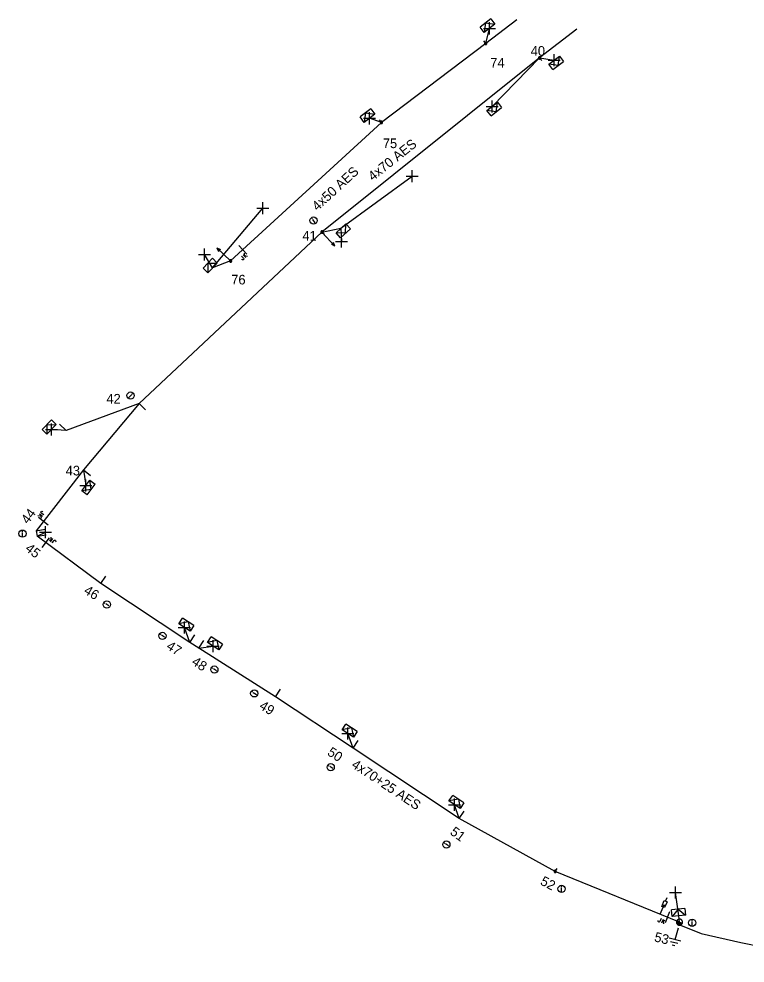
# Model space of a CAD drawing. Extents: x -540247 to -537390, y -1183887 to -1180355.
# Drawn here: x -537803.3 to -537727.9, y -1180528.4 to -1180430.4 of the extents above; entities that cross this region are included whole.
import ezdxf

# ---------------------------------------------------------------- set-up
doc = ezdxf.new("R2010")
doc.units = 0
for name, color, linetype in [('Vrstva 1', 7, 'Continuous'), ('Vrstva 10', 7, 'Continuous'), ('Vrstva 13', 7, 'Continuous'), ('Vrstva 14', 7, 'Continuous'), ('Vrstva 15', 7, 'Continuous'), ('Vrstva 16', 7, 'Continuous'), ('Vrstva 18', 7, 'Continuous'), ('Vrstva 2', 7, 'Continuous'), ('Vrstva 31', 7, 'Continuous'), ('Vrstva 34', 7, 'Continuous'), ('Vrstva 36', 7, 'Continuous'), ('Vrstva 5', 7, 'Continuous'), ('Vrstva 50', 7, 'Continuous'), ('Vrstva 51', 7, 'Continuous'), ('Vrstva 54', 7, 'Continuous'), ('Vrstva 59', 7, 'Continuous'), ('Vrstva 8', 7, 'Continuous'), ('Vrstva 9', 7, 'Continuous')]:
    doc.layers.add(name, color=color, linetype=linetype)

# ---------------------------------------------------------------- blocks, each defined once
blk = doc.blocks.new('NN440')
at = {"layer": 'Vrstva 2'}
for points in [[(0.63, 0), (0.63, 0.06), (0.62, 0.13), (0.6, 0.19), (0.58, 0.25), (0.55, 0.31), (0.51, 0.37), (0.47, 0.42), (0.42, 0.46), (0.37, 0.51), (0.32, 0.54), (0.26, 0.57), (0.2, 0.59), (0.13, 0.61), (0.07, 0.62), (0, 0.63), (-0.06, 0.62), (-0.13, 0.61), (-0.19, 0.59), (-0.26, 0.57), (-0.31, 0.54), (-0.37, 0.51), (-0.42, 0.46), (-0.47, 0.42), (-0.51, 0.37), (-0.54, 0.31), (-0.57, 0.25), (-0.6, 0.19), (-0.62, 0.13), (-0.63, 0.06), (-0.63, 0), (-0.63, -0.07), (-0.62, -0.14), (-0.6, -0.2), (-0.57, -0.26), (-0.54, -0.32), (-0.51, -0.37), (-0.47, -0.43), (-0.42, -0.47), (-0.37, -0.51), (-0.31, -0.55), (-0.26, -0.58), (-0.19, -0.6), (-0.13, -0.62), (-0.06, -0.63), (0, -0.63), (0.07, -0.63), (0.13, -0.62), (0.2, -0.6), (0.26, -0.58), (0.32, -0.55), (0.37, -0.51), (0.42, -0.47), (0.47, -0.43), (0.51, -0.37), (0.55, -0.32), (0.58, -0.26), (0.6, -0.2), (0.62, -0.14), (0.63, -0.07), (0.63, 0)], [(-0.63, 0), (0.63, 0)], [(-0.6, -0.18), (0.57, -0.18)], [(-0.51, -0.32), (0.5, -0.32)], [(-0.37, -0.47), (0.35, -0.47)]]:
    blk.add_lwpolyline(points, dxfattribs=at)
blk = doc.blocks.new('NN560')
at = {"layer": 'Vrstva 2'}
for points in [[(1.999, -0.001), (1.59, 0.141)], [(0, -0.001), (1.999, -0.001)], [(1.999, -0.001), (1.59, -0.134)]]:
    blk.add_lwpolyline(points, dxfattribs=at)
blk = doc.blocks.new('NN840')
at = {"layer": 'Vrstva 15'}
for points in [[(0.003, 0.619), (0.003, -0.631)], [(-0.745, -0.71), (-0.745, -0.66)], [(-0.73, -0.764), (-0.745, -0.71)], [(-0.657, -0.798), (-0.73, -0.764)], [(-0.627, -0.798), (-0.657, -0.798)], [(-0.558, -0.764), (-0.627, -0.798)], [(-0.538, -0.71), (-0.558, -0.764)], [(-0.538, -0.385), (-0.538, -0.71)], [(-0.332, -0.385), (-0.332, -0.798)], [(-0.332, -0.641), (-0.125, -0.385)], [(-0.263, -0.557), (-0.091, -0.798)]]:
    blk.add_lwpolyline(points, dxfattribs=at)
blk = doc.blocks.new('NN770')
at = {"layer": 'Vrstva 10'}
for p, q in [((0.002, 0.187), (0.002, 0.263)), ((0.002, -0.276), (0.002, 0.111))]:
    blk.add_line(p, q, dxfattribs=at)
blk.add_circle((0, -0.008), 0.375, dxfattribs=at)
blk = doc.blocks.new('NN800')
at = {"layer": 'Vrstva 1'}
for points in [[(-0.442, 0.442), (0.442, -0.442)], [(-0.442, -0.442), (0.442, 0.442)]]:
    blk.add_lwpolyline(points, dxfattribs=at)
blk = doc.blocks.new('NN820')
at = {"layer": 'Vrstva 13'}
for points in [[(-0.003, 0.004), (-0.003, -1.049)], [(-0.165, -0.813), (0.165, -0.813)], [(-0.165, -1.473), (-0.165, -0.813)], [(-0.003, -1.049), (-0.062, -0.926)], [(-0.003, -1.049), (0.057, -0.926)], [(0.165, -0.813), (0.165, -1.473)], [(0.165, -1.473), (-0.165, -1.473)], [(-0.003, -1.473), (-0.003, -1.871)]]:
    blk.add_lwpolyline(points, dxfattribs=at)
blk = doc.blocks.new('NN630')
at = {"layer": 'Vrstva 9'}
for points in [[(-0.003, -0.7), (-0.703, 0)], [(-0.703, -0.7), (-0.703, 0), (0.697, 0), (0.697, -0.7)], [(-0.703, -0.7), (0.697, -0.7)], [(-0.003, -0.7), (0.697, 0)]]:
    blk.add_lwpolyline(points, dxfattribs=at)
blk = doc.blocks.new('NN810')
at = {"layer": 'Vrstva 14'}
for points in [[(0.004, -0.64), (0.004, -1.89)], [(0.629, -1.89), (-0.621, -1.89)], [(0.388, -2.2), (-0.399, -2.2)], [(0.004, -2.515), (-0.124, -2.515)], [(0.137, -2.515), (0.004, -2.515)]]:
    blk.add_lwpolyline(points, dxfattribs=at)
blk = doc.blocks.new('NN500')
at = {"layer": 'Vrstva 2'}
for points in [[(0, -0.24), (0.02, -0.23), (0.05, -0.23), (0.07, -0.22), (0.09, -0.22), (0.12, -0.2), (0.14, -0.19), (0.16, -0.18), (0.17, -0.16), (0.19, -0.14), (0.2, -0.12), (0.21, -0.1), (0.22, -0.07), (0.23, -0.05), (0.23, -0.02), (0.23, 0), (0.23, 0.02), (0.23, 0.05), (0.22, 0.07), (0.21, 0.1), (0.2, 0.12), (0.19, 0.14), (0.17, 0.16), (0.16, 0.17), (0.14, 0.19), (0.12, 0.2), (0.09, 0.21), (0.07, 0.22), (0.05, 0.23), (0.02, 0.23), (0, 0.23), (-0.03, 0.23), (-0.05, 0.23), (-0.07, 0.22), (-0.1, 0.21), (-0.12, 0.2), (-0.14, 0.19), (-0.16, 0.17), (-0.18, 0.16), (-0.19, 0.14), (-0.2, 0.12), (-0.22, 0.1), (-0.22, 0.07), (-0.23, 0.05), (-0.23, 0.02), (-0.24, 0), (-0.23, -0.02), (-0.23, -0.05), (-0.22, -0.07), (-0.22, -0.1), (-0.2, -0.12), (-0.19, -0.14), (-0.18, -0.16), (-0.16, -0.18), (-0.14, -0.19), (-0.12, -0.2), (-0.1, -0.22), (-0.07, -0.22), (-0.05, -0.23), (-0.03, -0.23), (0, -0.24)], [(0, -0.24), (0.02, -0.23), (0.05, -0.23), (0.07, -0.22), (0.09, -0.22), (0.12, -0.2), (0.14, -0.19), (0.16, -0.18), (0.17, -0.16), (0.19, -0.14), (0.2, -0.12), (0.21, -0.1), (0.22, -0.07), (0.23, -0.05), (0.23, -0.02), (0.23, 0), (0.23, 0.02), (0.23, 0.05), (0.22, 0.07), (0.21, 0.1), (0.2, 0.12), (0.19, 0.14), (0.17, 0.16), (0.16, 0.17), (0.14, 0.19), (0.12, 0.2), (0.09, 0.21), (0.07, 0.22), (0.05, 0.23), (0.02, 0.23), (0, 0.23), (-0.03, 0.23), (-0.05, 0.23), (-0.07, 0.22), (-0.1, 0.21), (-0.12, 0.2), (-0.14, 0.19), (-0.16, 0.17), (-0.18, 0.16), (-0.19, 0.14), (-0.2, 0.12), (-0.22, 0.1), (-0.22, 0.07), (-0.23, 0.05), (-0.23, 0.02), (-0.24, 0), (-0.23, -0.02), (-0.23, -0.05), (-0.22, -0.07), (-0.22, -0.1), (-0.2, -0.12), (-0.19, -0.14), (-0.18, -0.16), (-0.16, -0.18), (-0.14, -0.19), (-0.12, -0.2), (-0.1, -0.22), (-0.07, -0.22), (-0.05, -0.23), (-0.03, -0.23), (0, -0.24)], [(0, -0.21), (0.02, -0.2), (0.04, -0.2), (0.06, -0.2), (0.08, -0.19), (0.1, -0.18), (0.12, -0.17), (0.14, -0.15), (0.15, -0.14), (0.16, -0.12), (0.18, -0.1), (0.19, -0.08), (0.19, -0.06), (0.2, -0.04), (0.2, -0.02), (0.2, 0), (0.2, 0.02), (0.2, 0.04), (0.19, 0.06), (0.19, 0.08), (0.18, 0.1), (0.16, 0.12), (0.15, 0.14), (0.14, 0.15), (0.12, 0.17), (0.1, 0.18), (0.08, 0.19), (0.06, 0.19), (0.04, 0.2), (0.02, 0.2), (0, 0.2), (-0.02, 0.2), (-0.04, 0.2), (-0.06, 0.19), (-0.08, 0.19), (-0.1, 0.18), (-0.12, 0.17), (-0.14, 0.15), (-0.15, 0.14), (-0.17, 0.12), (-0.18, 0.1), (-0.19, 0.08), (-0.2, 0.06), (-0.2, 0.04), (-0.21, 0.02), (-0.21, 0), (-0.21, -0.02), (-0.2, -0.04), (-0.2, -0.06), (-0.19, -0.08), (-0.18, -0.1), (-0.17, -0.12), (-0.15, -0.14), (-0.14, -0.15), (-0.12, -0.17), (-0.1, -0.18), (-0.08, -0.19), (-0.06, -0.2), (-0.04, -0.2), (-0.02, -0.2), (0, -0.21)], [(0, -0.18), (0.02, -0.18), (0.04, -0.17), (0.05, -0.17), (0.07, -0.16), (0.09, -0.15), (0.1, -0.14), (0.12, -0.13), (0.13, -0.12), (0.14, -0.1), (0.15, -0.09), (0.16, -0.07), (0.17, -0.05), (0.17, -0.04), (0.17, -0.02), (0.17, 0), (0.17, 0.02), (0.17, 0.04), (0.17, 0.05), (0.16, 0.07), (0.15, 0.09), (0.14, 0.1), (0.13, 0.12), (0.12, 0.13), (0.1, 0.14), (0.09, 0.15), (0.07, 0.16), (0.05, 0.17), (0.04, 0.17), (0.02, 0.17), (0, 0.18), (-0.02, 0.17), (-0.04, 0.17), (-0.06, 0.17), (-0.07, 0.16), (-0.09, 0.15), (-0.1, 0.14), (-0.12, 0.13), (-0.13, 0.12), (-0.14, 0.1), (-0.15, 0.09), (-0.16, 0.07), (-0.17, 0.05), (-0.17, 0.04), (-0.18, 0.02), (-0.18, 0), (-0.18, -0.02), (-0.17, -0.04), (-0.17, -0.05), (-0.16, -0.07), (-0.15, -0.09), (-0.14, -0.1), (-0.13, -0.12), (-0.12, -0.13), (-0.1, -0.14), (-0.09, -0.15), (-0.07, -0.16), (-0.06, -0.17), (-0.04, -0.17), (-0.02, -0.18), (0, -0.18)], [(0, -0.15), (0.01, -0.15), (0.03, -0.14), (0.04, -0.14), (0.06, -0.13), (0.07, -0.13), (0.08, -0.12), (0.1, -0.11), (0.11, -0.1), (0.12, -0.09), (0.13, -0.07), (0.13, -0.06), (0.14, -0.05), (0.14, -0.03), (0.14, -0.02), (0.14, 0), (0.14, 0.01), (0.14, 0.03), (0.14, 0.04), (0.13, 0.06), (0.13, 0.07), (0.12, 0.09), (0.11, 0.1), (0.1, 0.11), (0.08, 0.12), (0.07, 0.13), (0.06, 0.13), (0.04, 0.14), (0.03, 0.14), (0.01, 0.14), (0, 0.15), (-0.02, 0.14), (-0.03, 0.14), (-0.05, 0.14), (-0.06, 0.13), (-0.07, 0.13), (-0.09, 0.12), (-0.1, 0.11), (-0.11, 0.1), (-0.12, 0.09), (-0.13, 0.07), (-0.13, 0.06), (-0.14, 0.04), (-0.14, 0.03), (-0.15, 0.01), (-0.15, 0), (-0.15, -0.02), (-0.14, -0.03), (-0.14, -0.05), (-0.13, -0.06), (-0.13, -0.07), (-0.12, -0.09), (-0.11, -0.1), (-0.1, -0.11), (-0.09, -0.12), (-0.07, -0.13), (-0.06, -0.13), (-0.05, -0.14), (-0.03, -0.14), (-0.02, -0.15), (0, -0.15)], [(0, -0.12), (0.01, -0.12), (0.02, -0.11), (0.03, -0.11), (0.05, -0.11), (0.06, -0.1), (0.07, -0.09), (0.08, -0.09), (0.09, -0.08), (0.09, -0.07), (0.1, -0.06), (0.11, -0.05), (0.11, -0.04), (0.11, -0.02), (0.11, -0.01), (0.12, 0), (0.11, 0.01), (0.11, 0.02), (0.11, 0.04), (0.11, 0.05), (0.1, 0.06), (0.09, 0.07), (0.09, 0.08), (0.08, 0.09), (0.07, 0.09), (0.06, 0.1), (0.05, 0.11), (0.03, 0.11), (0.02, 0.11), (0.01, 0.12), (0, 0.12), (-0.01, 0.12), (-0.03, 0.11), (-0.04, 0.11), (-0.05, 0.11), (-0.06, 0.1), (-0.07, 0.09), (-0.08, 0.09), (-0.09, 0.08), (-0.1, 0.07), (-0.1, 0.06), (-0.11, 0.05), (-0.11, 0.04), (-0.12, 0.02), (-0.12, 0.01), (-0.12, 0), (-0.12, -0.01), (-0.12, -0.02), (-0.11, -0.04), (-0.11, -0.05), (-0.1, -0.06), (-0.1, -0.07), (-0.09, -0.08), (-0.08, -0.09), (-0.07, -0.09), (-0.06, -0.1), (-0.05, -0.11), (-0.04, -0.11), (-0.03, -0.11), (-0.01, -0.12), (0, -0.12)], [(0, -0.09), (0.01, -0.09), (0.02, -0.09), (0.03, -0.08), (0.03, -0.08), (0.04, -0.08), (0.05, -0.07), (0.06, -0.07), (0.06, -0.06), (0.07, -0.05), (0.07, -0.04), (0.08, -0.04), (0.08, -0.03), (0.08, -0.02), (0.09, -0.01), (0.09, 0), (0.09, 0.01), (0.08, 0.02), (0.08, 0.03), (0.08, 0.03), (0.07, 0.04), (0.07, 0.05), (0.06, 0.06), (0.06, 0.06), (0.05, 0.07), (0.04, 0.07), (0.03, 0.08), (0.03, 0.08), (0.02, 0.08), (0.01, 0.09), (0, 0.09), (-0.01, 0.09), (-0.02, 0.08), (-0.03, 0.08), (-0.04, 0.08), (-0.04, 0.07), (-0.05, 0.07), (-0.06, 0.06), (-0.07, 0.06), (-0.07, 0.05), (-0.08, 0.04), (-0.08, 0.03), (-0.08, 0.03), (-0.09, 0.02), (-0.09, 0.01), (-0.09, 0), (-0.09, -0.01), (-0.09, -0.02), (-0.08, -0.03), (-0.08, -0.04), (-0.08, -0.04), (-0.07, -0.05), (-0.07, -0.06), (-0.06, -0.07), (-0.05, -0.07), (-0.04, -0.08), (-0.04, -0.08), (-0.03, -0.08), (-0.02, -0.09), (-0.01, -0.09), (0, -0.09)], [(0, -0.06), (0, -0.06), (0.01, -0.06), (0.02, -0.05), (0.02, -0.05), (0.03, -0.05), (0.03, -0.05), (0.04, -0.04), (0.04, -0.04), (0.05, -0.03), (0.05, -0.03), (0.05, -0.02), (0.05, -0.02), (0.05, -0.01), (0.06, -0.01), (0.06, 0), (0.06, 0.01), (0.05, 0.01), (0.05, 0.02), (0.05, 0.02), (0.05, 0.03), (0.05, 0.03), (0.04, 0.04), (0.04, 0.04), (0.03, 0.05), (0.03, 0.05), (0.02, 0.05), (0.02, 0.05), (0.01, 0.06), (0, 0.06), (0, 0.06), (-0.01, 0.06), (-0.01, 0.06), (-0.02, 0.05), (-0.02, 0.05), (-0.03, 0.05), (-0.03, 0.05), (-0.04, 0.04), (-0.04, 0.04), (-0.05, 0.03), (-0.05, 0.03), (-0.05, 0.02), (-0.06, 0.02), (-0.06, 0.01), (-0.06, 0.01), (-0.06, 0), (-0.06, -0.01), (-0.06, -0.01), (-0.06, -0.02), (-0.05, -0.02), (-0.05, -0.03), (-0.05, -0.03), (-0.04, -0.04), (-0.04, -0.04), (-0.03, -0.05), (-0.03, -0.05), (-0.02, -0.05), (-0.02, -0.05), (-0.01, -0.06), (-0.01, -0.06), (0, -0.06)], [(0, -0.03), (0, -0.03), (0, -0.03), (0.01, -0.03), (0.01, -0.03), (0.01, -0.02), (0.02, -0.02), (0.02, -0.02), (0.02, -0.02), (0.02, -0.02), (0.02, -0.01), (0.02, -0.01), (0.03, -0.01), (0.03, -0.01), (0.03, 0), (0.03, 0), (0.03, 0), (0.03, 0.01), (0.03, 0.01), (0.02, 0.01), (0.02, 0.01), (0.02, 0.02), (0.02, 0.02), (0.02, 0.02), (0.02, 0.02), (0.01, 0.02), (0.01, 0.02), (0.01, 0.03), (0, 0.03), (0, 0.03), (0, 0.03), (0, 0.03), (-0.01, 0.03), (-0.01, 0.03), (-0.01, 0.02), (-0.02, 0.02), (-0.02, 0.02), (-0.02, 0.02), (-0.02, 0.02), (-0.02, 0.02), (-0.03, 0.01), (-0.03, 0.01), (-0.03, 0.01), (-0.03, 0.01), (-0.03, 0), (-0.03, 0), (-0.03, 0), (-0.03, -0.01), (-0.03, -0.01), (-0.03, -0.01), (-0.03, -0.01), (-0.02, -0.02), (-0.02, -0.02), (-0.02, -0.02), (-0.02, -0.02), (-0.02, -0.02), (-0.01, -0.03), (-0.01, -0.03), (-0.01, -0.03), (0, -0.03), (0, -0.03)], [(0.23, 0), (0.7, 0)]]:
    blk.add_lwpolyline(points, dxfattribs=at)
blk = doc.blocks.new('NN510')
at = {"layer": 'Vrstva 2'}
blk.add_lwpolyline([(0.001, 0.002), (0.001, 0.939)], dxfattribs=at)

msp = doc.modelspace()

# ---------------------------------------------------------------- linework, layer by layer
at = {"layer": 'Vrstva 5'}
msp.add_lwpolyline([(-537734.68, -1180524.19), (-537734.74, -1180524.45), (-537732.42, -1180525.38), (-537728.3, -1180526.32), (-537725.94, -1180526.78), (-537719.916, -1180528.443), (-537719.145, -1180526.532), (-537715.575, -1180518.142), (-537712.055, -1180509.59), (-537710.072, -1180505.214), (-537708.029, -1180501.425), (-537707.177, -1180501.531), (-537706.489, -1180502.117), (-537706.751, -1180502.897)], dxfattribs=at)
at = {"layer": 'Vrstva 50'}
for points in [[(-537751.585, -1180430.526), (-537754.798, -1180432.973), (-537765.621, -1180441.171), (-537781.283, -1180455.558)], [(-537745.355, -1180431.488), (-537749.207, -1180434.474), (-537771.799, -1180452.548), (-537790.796, -1180470.357), (-537796.576, -1180477.236), (-537801.465, -1180483.556), (-537801.379, -1180484.135)], [(-537734.68, -1180524.19), (-537747.587, -1180518.919), (-537757.57, -1180513.434), (-537768.551, -1180506.129), (-537776.628, -1180500.802), (-537784.582, -1180495.757), (-537785.515, -1180495.157), (-537794.753, -1180489.046), (-537801.379, -1180484.135)]]:
    msp.add_lwpolyline(points, dxfattribs=at)
at = {"layer": 'Vrstva 54'}
for points in [[(-537754.798, -1180432.973), (-537754.408, -1180431.407)], [(-537749.207, -1180434.474), (-537754.134, -1180439.51)], [(-537749.207, -1180434.474), (-537747.693, -1180434.708)], [(-537765.621, -1180441.171), (-537766.869, -1180440.746)], [(-537771.799, -1180452.548), (-537769.828, -1180452.165)], [(-537790.796, -1180470.357), (-537798.371, -1180473.162), (-537799.881, -1180473.043)], [(-537796.576, -1180477.236), (-537796.318, -1180478.861)], [(-537801.379, -1180484.135), (-537800.5, -1180483.693)], [(-537785.515, -1180495.157), (-537786.09, -1180493.599)], [(-537784.582, -1180495.757), (-537783.115, -1180495.545)], [(-537768.551, -1180506.129), (-537769.131, -1180504.609)], [(-537757.57, -1180513.434), (-537758.033, -1180511.997)], [(-537734.68, -1180524.19), (-537734.746, -1180523.539)]]:
    msp.add_lwpolyline(points, dxfattribs=at)
at = {"layer": 'Vrstva 59'}
for points in [[(-537769.828, -1180452.165), (-537762.424, -1180446.762)], [(-537783.161, -1180456.272), (-537777.94, -1180450.067)], [(-537769.828, -1180452.165), (-537769.787, -1180453.521)], [(-537783.161, -1180456.272), (-537783.983, -1180454.894)], [(-537734.746, -1180523.539), (-537735.105, -1180521.098)]]:
    msp.add_lwpolyline(points, dxfattribs=at)
at = {"layer": 'Vrstva 8'}
msp.add_lwpolyline([(-537781.283, -1180455.558), (-537783.161, -1180456.272)], dxfattribs=at)

# ---------------------------------------------------------------- block references
at = {"layer": 'Vrstva 13'}
for name, p, xscale, yscale, rotation in [('NN500', (-537754.798, -1180432.973), 0.5, 0.5, 127.17399988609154), ('NN500', (-537749.207, -1180434.474), 0.5, 0.5000000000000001, -52.07499995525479), ('NN500', (-537765.621, -1180441.171), 0.5, 0.5, 126.94599993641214), ('NN500', (-537771.799, -1180452.548), 0.5000000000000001, 0.4999999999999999, -47.0440000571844), ('NN500', (-537781.283, -1180455.558), 0.5, 0.5, 135.89599999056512), ('NN500', (-537747.587, -1180518.919), 0.5, 0.5, 57.11000012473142), ('NN440', (-537734.68, -1180524.19), 0.49999999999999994, 0.5, -18.592019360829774)]:
    msp.add_blockref(name, p, dxfattribs=dict(at, xscale=xscale, yscale=yscale, rotation=rotation))
for name, p, rotation in [('NN560', (-537771.799, -1180452.548), -47.52668892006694), ('NN560', (-537781.283, -1180455.558), 136.22300564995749), ('NN510', (-537790.796, -1180470.357), -134.41280270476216), ('NN510', (-537798.371, -1180473.163), 45.38453058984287), ('NN510', (-537796.576, -1180477.236), -127.59175561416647), ('NN510', (-537801.466, -1180483.556), -80.66400835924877), ('NN510', (-537801.38, -1180484.135), -81.0842056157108), ('NN510', (-537794.753, -1180489.046), -33.38147499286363), ('NN510', (-537785.515, -1180495.157), -33.38147495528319), ('NN510', (-537784.582, -1180495.757), -32.78255276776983), ('NN510', (-537776.628, -1180500.802), -32.782552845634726), ('NN510', (-537768.552, -1180506.129), -33.117605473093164), ('NN510', (-537757.57, -1180513.435), -33.62559985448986)]:
    msp.add_blockref(name, p, dxfattribs=dict(at, rotation=rotation))
at = {"layer": 'Vrstva 15', "rotation": -14.53206386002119}
msp.add_blockref('NN810', (-537734.68, -1180524.19), dxfattribs=at)
at = {"layer": 'Vrstva 16', "rotation": 157.78500807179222}
msp.add_blockref('NN820', (-537736.687, -1180523.37), dxfattribs=at)
at = {"layer": 'Vrstva 18'}
for p, rotation in [((-537780.016, -1180454.394), 42.5703582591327), ((-537800.714, -1180482.585), -127.7246749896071), ((-537800.47, -1180484.809), 143.45522495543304), ((-537735.941, -1180523.675), -22.214991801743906)]:
    msp.add_blockref('NN840', p, dxfattribs=dict(at, rotation=rotation))
at = {"layer": 'Vrstva 31'}
for p, rotation in [((-537754.408, -1180431.407), -142.82574437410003), ((-537747.693, -1180434.708), 37.92500278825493), ((-537754.134, -1180439.51), 38.34447494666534), ((-537766.869, -1180440.746), -143.0537833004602), ((-537769.828, -1180452.165), 42.956211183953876), ((-537783.161, -1180456.272), -134.1039333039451), ((-537799.881, -1180473.043), -134.61546945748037), ((-537796.318, -1180478.861), 52.408244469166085), ((-537786.09, -1180493.599), 146.61852500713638), ((-537783.115, -1180495.545), 147.21744726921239), ((-537769.131, -1180504.609), 146.88239437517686), ((-537758.033, -1180511.997), 146.37440010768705), ((-537734.746, -1180523.539), -174.18333101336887)]:
    msp.add_blockref('NN630', p, dxfattribs=dict(at, rotation=rotation))
at = {"layer": 'Vrstva 34'}
for p, rotation in [((-537754.408, -1180431.407), 45), ((-537747.693, -1180434.708), 45), ((-537754.134, -1180439.51), 45), ((-537766.869, -1180440.746), 44.99999995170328), ((-537762.424, -1180446.762), 45), ((-537777.94, -1180450.067), 44.99999995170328), ((-537769.787, -1180453.521), 45.00000009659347), ((-537783.983, -1180454.894), 45), ((-537799.881, -1180473.043), 45), ((-537796.318, -1180478.861), 45), ((-537800.5, -1180483.693), 45), ((-537786.09, -1180493.599), 45), ((-537783.115, -1180495.545), 45), ((-537769.131, -1180504.609), 45), ((-537758.033, -1180511.997), 45), ((-537735.105, -1180521.098), 45)]:
    msp.add_blockref('NN800', p, dxfattribs=dict(at, rotation=rotation))
at = {"layer": 'Vrstva 36'}
for p, rotation in [((-537772.677, -1180451.353), 33.02386661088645), ((-537791.669, -1180469.523), -44.437869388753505), ((-537794.145, -1180491.208), 56.66601388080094), ((-537788.374, -1180494.473), 56.66601388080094), ((-537782.981, -1180497.966), 57.242730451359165), ((-537778.838, -1180500.436), 57.242730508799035), ((-537770.904, -1180508.097), 56.835255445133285), ((-537758.894, -1180516.12), 56.39466391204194)]:
    msp.add_blockref('NN770', p, dxfattribs=dict(at, rotation=rotation))
for p in [(-537802.894, -1180483.851), (-537746.926, -1180520.731), (-537733.368, -1180524.245)]:
    msp.add_blockref('NN770', p, dxfattribs=at)

# ---------------------------------------------------------------- texts
at = {"layer": 'Vrstva 14'}
for s, p in [('40', (-537750.131, -1180434.249)), ('74', (-537754.329, -1180435.477)), ('75', (-537765.482, -1180443.841)), ('41', (-537773.836, -1180453.439)), ('76', (-537781.22, -1180457.991)), ('42', (-537794.182, -1180470.358)), ('43', (-537798.409, -1180477.819))]:
    msp.add_text(s, height=1, dxfattribs=at).set_placement(p)
for s, rotation, p in [('44', 53.713, (-537802.323, -1180482.933)), ('45', 321.606, (-537802.692, -1180485.552)), ('46', 328.883, (-537796.607, -1180490.019)), ('47', 327.509, (-537788.041, -1180495.77)), ('48', 326.572, (-537785.411, -1180497.375)), ('49', 328.267, (-537778.396, -1180501.974)), ('50', 326.461, (-537771.326, -1180506.778)), ('51', 323.385, (-537758.585, -1180515.001)), ('52', 332.178, (-537749.219, -1180520.239)), ('53', 346.534, (-537737.365, -1180526.172))]:
    msp.add_text(s, height=1, rotation=rotation, dxfattribs=at).set_placement(p)
at = {"layer": 'Vrstva 51'}
for s, rotation, p in [('4x70 AES', 38.66, (-537766.517, -1180447.302)), ('4x50 AES', 42.57, (-537772.281, -1180450.414)), ('4x70+25 AES', 326.463, (-537768.821, -1180508.06))]:
    msp.add_text(s, height=1, rotation=rotation, dxfattribs=at).set_placement(p)

doc.saveas('drawing.dxf')
